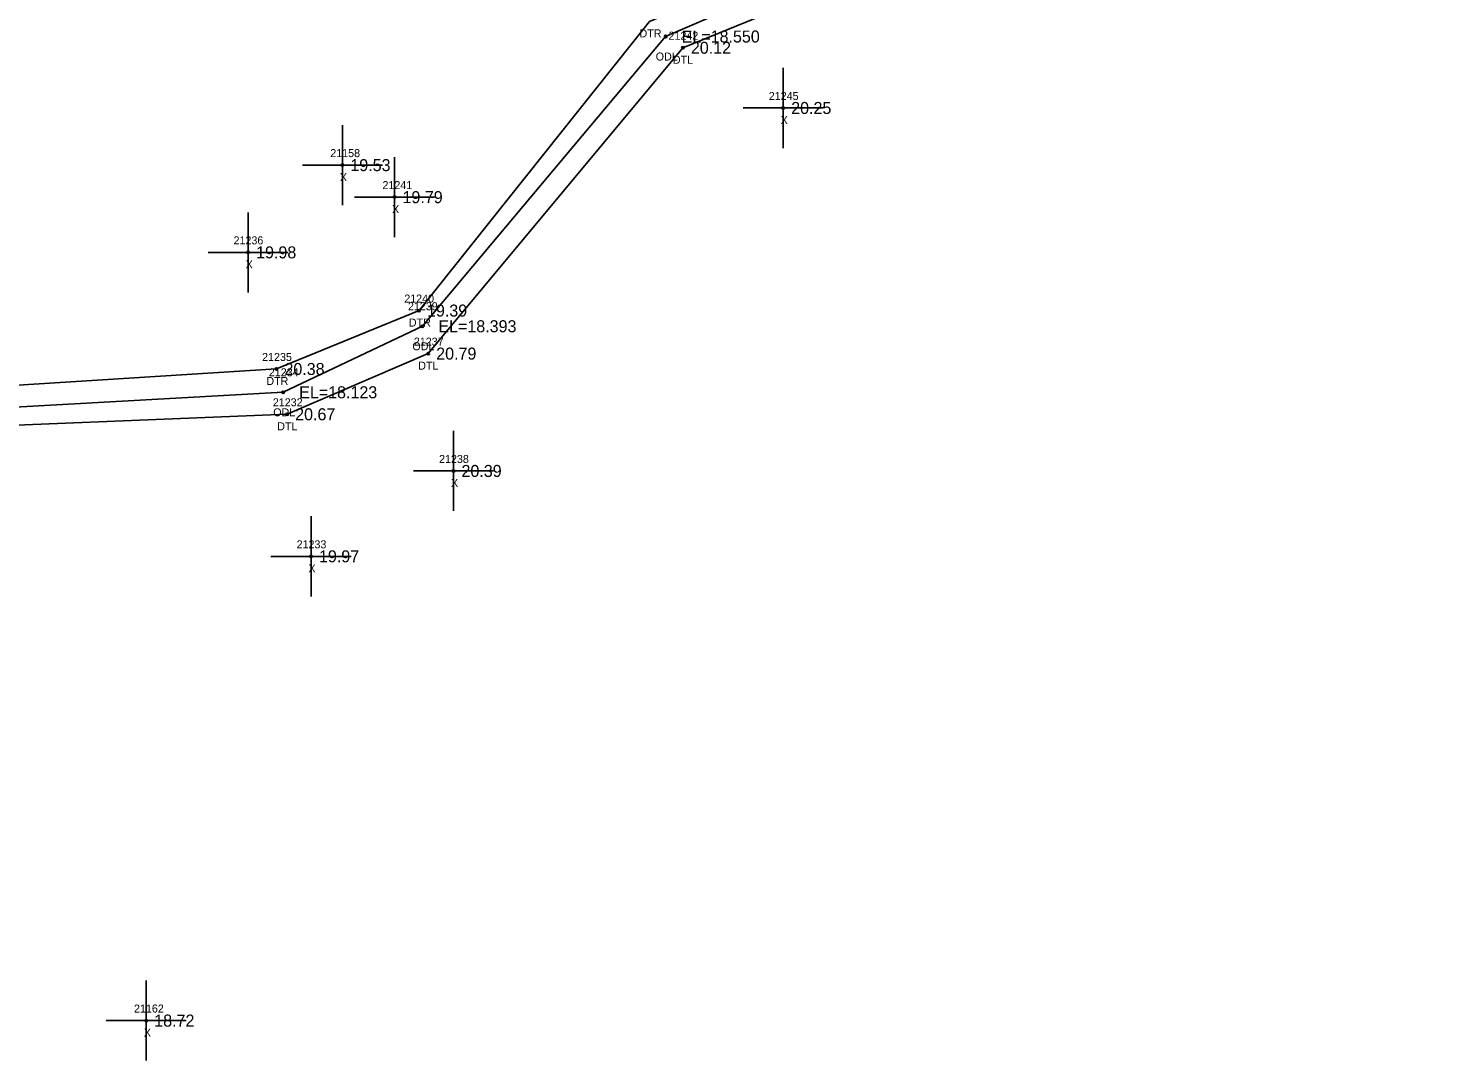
# Model space of a CAD drawing. Extents: x 2655177 to 2656219, y 761780 to 764748.
# Drawn here: x 2655506.1 to 2655683.7, y 761924.8 to 762053.8 of the extents above; entities that cross this region are included whole.
import ezdxf

# ---------------------------------------------------------------- set-up
doc = ezdxf.new("R2010")
doc.units = 0
for name, color, linetype in [('RD_EX_H2O', 7, 'Continuous'), ('RD_EX_H2O_txCode', 7, 'Continuous'), ('RD_EX_Misc', 7, 'Continuous'), ('RD_EX_Misc_txCode', 7, 'Continuous'), ('RD_EX_TX_H2O_ELEV', 7, 'Continuous'), ('RD_EX_TX_Misc_ELEV', 7, 'Continuous'), ('RD_SMD_Locator', 7, 'Continuous')]:
    doc.layers.add(name, color=color, linetype=linetype)

msp = doc.modelspace()

# ---------------------------------------------------------------- linework, layer by layer
at = {"layer": 'RD_EX_H2O'}
for points in [[(2655458.25, 762004.65), (2655489.16, 762003.6), (2655538.42, 762005.59), (2655556.05, 762013.17), (2655587.88, 762051.39), (2655643.4, 762074.04), (2655655.85, 762091.76), (2655681.86, 762140.14), (2655683.72, 762146.53), (2655664.39, 762201.23), (2655621.98, 762271.36), (2655558.86, 762321.08)], [(2655459.71, 762010.57), (2655488.92, 762008.22), (2655537.08, 762011.25), (2655554.9, 762018.55), (2655583.72, 762054.68), (2655639.44, 762078.76), (2655651.66, 762094.07), (2655673.82, 762140.27), (2655676.22, 762150.22), (2655658.16, 762196.88), (2655618.83, 762267.48), (2655556.47, 762317.07), (2655558.86, 762321.08)], [(2655456.91, 762008.75), (2655489.44, 762005.64), (2655537.92, 762008.34), (2655555.32, 762016.59), (2655585.73, 762052.79), (2655641.23, 762076.72), (2655654.31, 762091.55), (2655679.19, 762140.68), (2655679.13, 762150.47), (2655660.06, 762199), (2655620.4, 762269.42), (2655559.84, 762317.9)]]:
    msp.add_lwpolyline(points, dxfattribs=at)
at = {"layer": 'RD_EX_Misc'}
for p, q in [((2655600.42, 762038.86), (2655600.42, 762048.86)), ((2655595.42, 762043.86), (2655605.42, 762043.86)), ((2655545.32, 762031.72), (2655545.32, 762041.72)), ((2655540.32, 762036.72), (2655550.32, 762036.72)), ((2655551.84, 762027.72), (2655551.84, 762037.72)), ((2655546.84, 762032.72), (2655556.84, 762032.72)), ((2655533.54, 762020.82), (2655533.54, 762030.82)), ((2655528.54, 762025.82), (2655538.54, 762025.82)), ((2655559.21, 761993.51), (2655559.21, 762003.51)), ((2655554.21, 761998.51), (2655564.21, 761998.51)), ((2655541.4, 761982.84), (2655541.4, 761992.84)), ((2655536.4, 761987.84), (2655546.4, 761987.84)), ((2655520.81, 761924.84), (2655520.81, 761934.84)), ((2655515.81, 761929.84), (2655525.81, 761929.84))]:
    msp.add_line(p, q, dxfattribs=at)
at = {"layer": 'RD_SMD_Locator'}
for centre in [(2655585.73, 762052.79), (2655587.88, 762051.39), (2655600.42, 762043.86), (2655545.32, 762036.72), (2655551.84, 762032.72), (2655533.54, 762025.82), (2655554.9, 762018.55), (2655555.32, 762016.59), (2655556.05, 762013.17), (2655537.08, 762011.25), (2655537.92, 762008.34), (2655538.42, 762005.59), (2655559.21, 761998.51), (2655541.4, 761987.84), (2655520.81, 761929.84)]:
    msp.add_circle(centre, 0.15, dxfattribs=at)

# ---------------------------------------------------------------- texts
at = {"layer": 'RD_EX_H2O_txCode'}
for s, p in [('DTR', (2655582.46, 762052.68)), ('21242', (2655586.09, 762052.39)), ('ODL', (2655584.49, 762049.79)), ('DTL', (2655586.64, 762049.39)), ('21240', (2655553.06, 762019.55)), ('21239', (2655553.52, 762018.59)), ('DTR', (2655553.63, 762016.55)), ('21237', (2655554.26, 762014.17)), ('ODL', (2655554.07, 762013.59)), ('21235', (2655535.29, 762012.25)), ('DTL', (2655554.81, 762011.17)), ('DTR', (2655535.82, 762009.25)), ('21234', (2655536.13, 762010.34)), ('21232', (2655536.63, 762006.59)), ('ODL', (2655536.68, 762005.34)), ('DTL', (2655537.18, 762003.59))]:
    msp.add_text(s, height=1, dxfattribs=at).set_placement(p)
at = {"layer": 'RD_EX_Misc_txCode'}
for s, p in [('21245', (2655598.62, 762044.86)), ('X', (2655600.1, 762041.86)), ('21158', (2655543.81, 762037.72)), ('X', (2655545.01, 762034.72)), ('21241', (2655550.33, 762033.72)), ('X', (2655551.53, 762030.72)), ('21236', (2655531.72, 762026.82)), ('X', (2655533.23, 762023.82)), ('21238', (2655557.41, 761999.51)), ('X', (2655558.9, 761996.51)), ('21233', (2655539.6, 761988.84)), ('X', (2655541.08, 761985.84)), ('21162', (2655519.28, 761930.84)), ('X', (2655520.5, 761927.84))]:
    msp.add_text(s, height=1, dxfattribs=at).set_placement(p)
at = {"layer": 'RD_EX_TX_H2O_ELEV'}
for s, p in [('EL=18.550', (2655587.73, 762052.04)), ('20.12', (2655588.88, 762050.64)), ('19.39', (2655555.9, 762017.8)), ('EL=18.393', (2655557.32, 762015.84)), ('20.79', (2655557.05, 762012.42)), ('20.38', (2655538.08, 762010.5)), ('EL=18.123', (2655539.92, 762007.59)), ('20.67', (2655539.42, 762004.84))]:
    msp.add_text(s, height=1.5, dxfattribs=at).set_placement(p)
at = {"layer": 'RD_EX_TX_Misc_ELEV'}
for s, p in [('20.25', (2655601.42, 762043.11)), ('19.53', (2655546.32, 762035.97)), ('19.79', (2655552.84, 762031.97)), ('19.98', (2655534.54, 762025.07)), ('20.39', (2655560.21, 761997.76)), ('19.97', (2655542.4, 761987.09)), ('18.72', (2655521.81, 761929.09))]:
    msp.add_text(s, height=1.5, dxfattribs=at).set_placement(p)

doc.saveas('drawing.dxf')
